Omron CX-Programmer project NuevoProyecto (CX-Programmer 9.50)

# PLC NewPLC1: CP1L-E EM

## Program P16_3 (cyclic task 0)
Local symbols
Etapa_0 10.00 BOOL
Etapa_1 10.01 BOOL
Etapa_10 10.10 BOOL
Etapa_11 10.11 BOOL
Etapa_12 10.12 BOOL
Etapa_13 10.13 BOOL
Etapa_14 10.14 BOOL
Etapa_15 10.15 BOOL
Etapa_2 10.02 BOOL
Etapa_20 11.01 BOOL
Etapa_21 11.02 BOOL
Etapa_22 11.03 BOOL
Etapa_3 10.03 BOOL
Etapa_4 10.04 BOOL
Etapa_5 10.05 BOOL
Etapa_6 10.06 BOOL
Etapa_7 10.07 BOOL
Etapa_8 10.08 BOOL
Etapa_9 10.09 BOOL
Etapa_entrada_macroetapa 11.00 BOOL
Etapa_salida_macroetapa 11.04 BOOL
F1 0.02 BOOL
F2 0.03 BOOL
F3 0.04 BOOL
F4 0.05 BOOL
F5 0.06 BOOL
F6 0.07 BOOL
F7 0.08 BOOL
F8 0.09 BOOL
KB 100.01 BOOL
KD 100.02 BOOL
KI 100.03 BOOL
KS 100.00 BOOL
PD 0.00 BOOL
PI 0.01 BOOL

### Section Sección1_Programa_principal
; Programa principal (Etapas 0 ... 23)

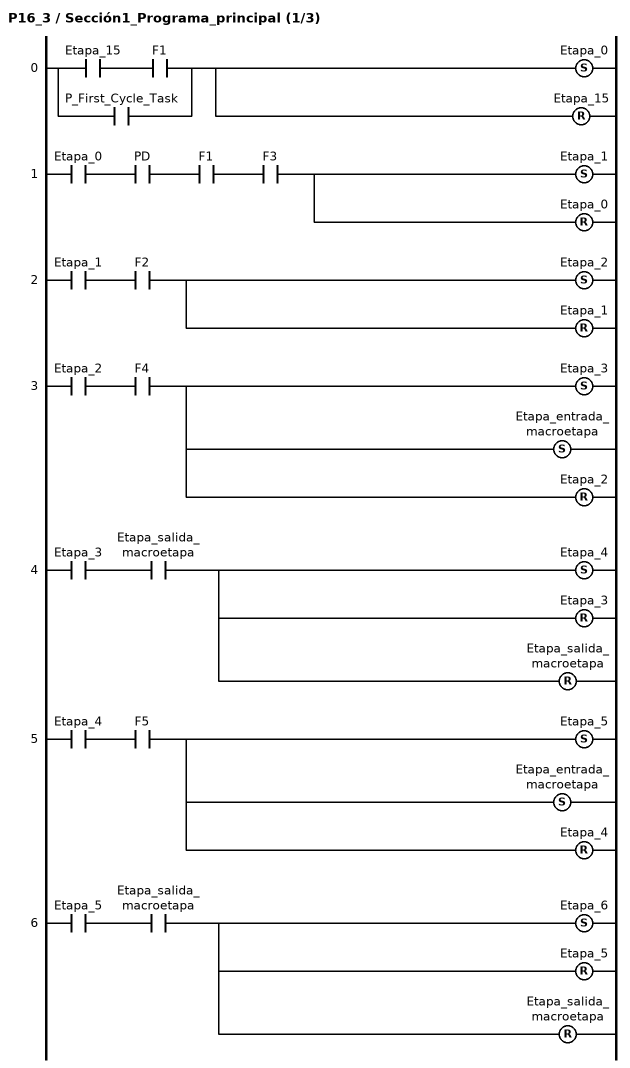
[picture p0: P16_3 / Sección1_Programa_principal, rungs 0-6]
; rung 0
LD Etapa_15
AND F1
OR P_First_Cycle_Task
SET Etapa_0
RSET Etapa_15
; rung 1
LD Etapa_0
AND PD
AND F1
AND F3
SET Etapa_1
RSET Etapa_0
; rung 2
LD Etapa_1
AND F2
SET Etapa_2
RSET Etapa_1
; rung 3
LD Etapa_2
AND F4
SET Etapa_3
SET Etapa_entrada_macroetapa
RSET Etapa_2
; rung 4
LD Etapa_3
AND Etapa_salida_macroetapa
SET Etapa_4
RSET Etapa_3
RSET Etapa_salida_macroetapa
; rung 5
LD Etapa_4
AND F5
SET Etapa_5
SET Etapa_entrada_macroetapa
RSET Etapa_4
; rung 6
LD Etapa_5
AND Etapa_salida_macroetapa
SET Etapa_6
RSET Etapa_5
RSET Etapa_salida_macroetapa

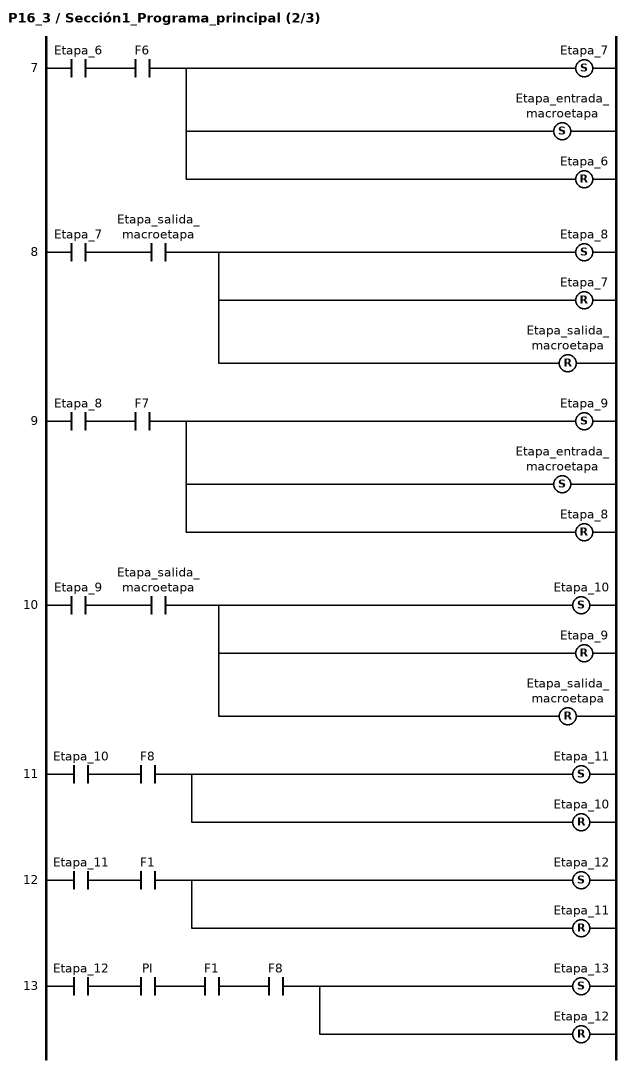
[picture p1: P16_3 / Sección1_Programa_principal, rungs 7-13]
; rung 7
LD Etapa_6
AND F6
SET Etapa_7
SET Etapa_entrada_macroetapa
RSET Etapa_6
; rung 8
LD Etapa_7
AND Etapa_salida_macroetapa
SET Etapa_8
RSET Etapa_7
RSET Etapa_salida_macroetapa
; rung 9
LD Etapa_8
AND F7
SET Etapa_9
SET Etapa_entrada_macroetapa
RSET Etapa_8
; rung 10
LD Etapa_9
AND Etapa_salida_macroetapa
SET Etapa_10
RSET Etapa_9
RSET Etapa_salida_macroetapa
; rung 11
LD Etapa_10
AND F8
SET Etapa_11
RSET Etapa_10
; rung 12
LD Etapa_11
AND F1
SET Etapa_12
RSET Etapa_11
; rung 13
LD Etapa_12
AND PI
AND F1
AND F8
SET Etapa_13
RSET Etapa_12

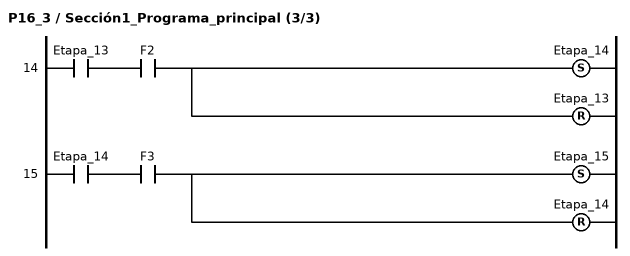
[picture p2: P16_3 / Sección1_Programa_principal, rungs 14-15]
; rung 14
LD Etapa_13
AND F2
SET Etapa_14
RSET Etapa_13
; rung 15
LD Etapa_14
AND F3
SET Etapa_15
RSET Etapa_14

### Section Sección2_Macroetapa

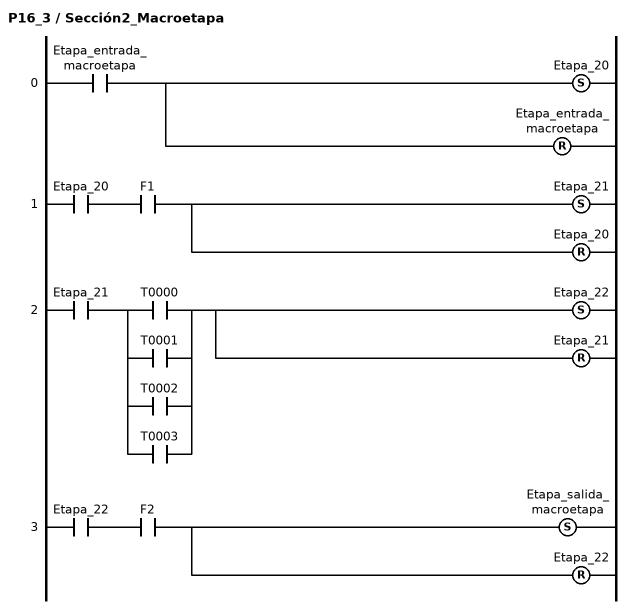
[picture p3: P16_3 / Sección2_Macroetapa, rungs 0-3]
; rung 0
LD Etapa_entrada_macroetapa
SET Etapa_20
RSET Etapa_entrada_macroetapa
; rung 1
LD Etapa_20
AND F1
SET Etapa_21
RSET Etapa_20
; rung 2
LD Etapa_21
LD T0000
OR T0001
OR T0002
OR T0003
ANDLD
SET Etapa_22
RSET Etapa_21
; rung 3
LD Etapa_22
AND F2
SET Etapa_salida_macroetapa
RSET Etapa_22

### Section Sección3_Temporizadores

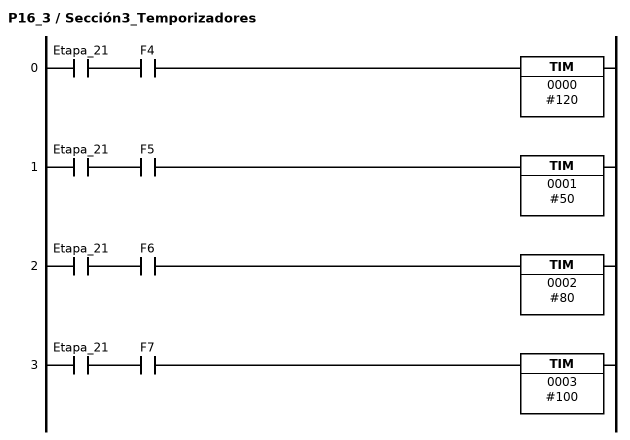
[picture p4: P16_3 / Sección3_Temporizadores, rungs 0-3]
; rung 0
LD Etapa_21
AND F4
TIM 0000 #120
; rung 1
LD Etapa_21
AND F5
TIM 0001 #50
; rung 2
LD Etapa_21
AND F6
TIM 0002 #80
; rung 3
LD Etapa_21
AND F7
TIM 0003 #100

### Section Sección4_Salidas

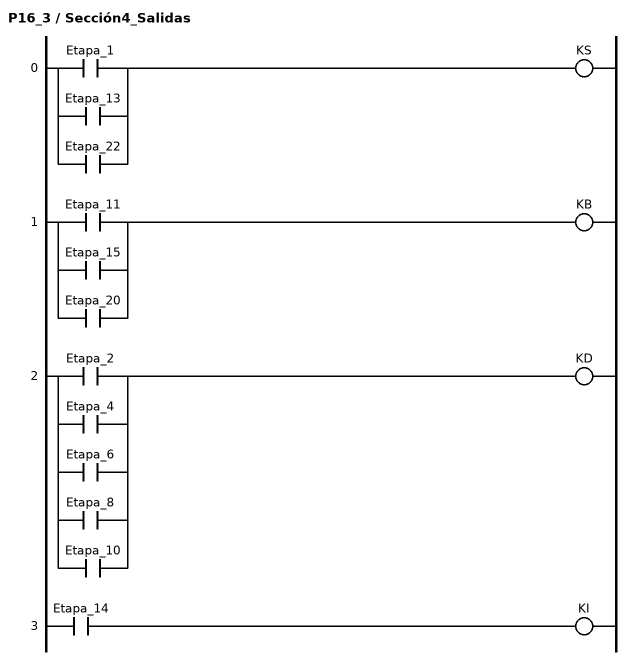
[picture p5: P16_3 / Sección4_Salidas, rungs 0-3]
; rung 0
LD Etapa_1
OR Etapa_13
OR Etapa_22
OUT KS
; rung 1
LD Etapa_11
OR Etapa_15
OR Etapa_20
OUT KB
; rung 2
LD Etapa_2
OR Etapa_4
OR Etapa_6
OR Etapa_8
OR Etapa_10
OUT KD
; rung 3
LD Etapa_14
OUT KI

### Section Sección5_END
; rung 0: Fin de programa
END(001)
